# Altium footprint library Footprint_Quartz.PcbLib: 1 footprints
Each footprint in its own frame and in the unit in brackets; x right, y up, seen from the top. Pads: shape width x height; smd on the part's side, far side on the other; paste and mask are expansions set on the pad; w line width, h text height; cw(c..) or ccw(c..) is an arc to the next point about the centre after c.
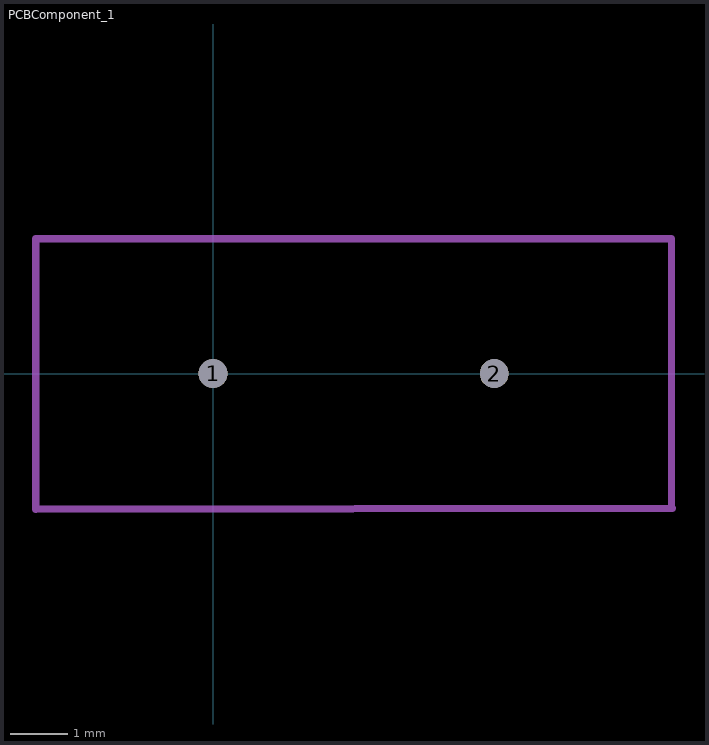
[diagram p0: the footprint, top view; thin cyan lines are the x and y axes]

## PCBComponent_1 [mm]
pads (2):
  round 0.5 hole 0.5: 1(0,0) 2(4.877,0)
Mechanical 1:
  lines w0.127: 7.95,-2.324 7.95,2.337 -3.073,2.337 -3.073,-2.349 7.963,-2.337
